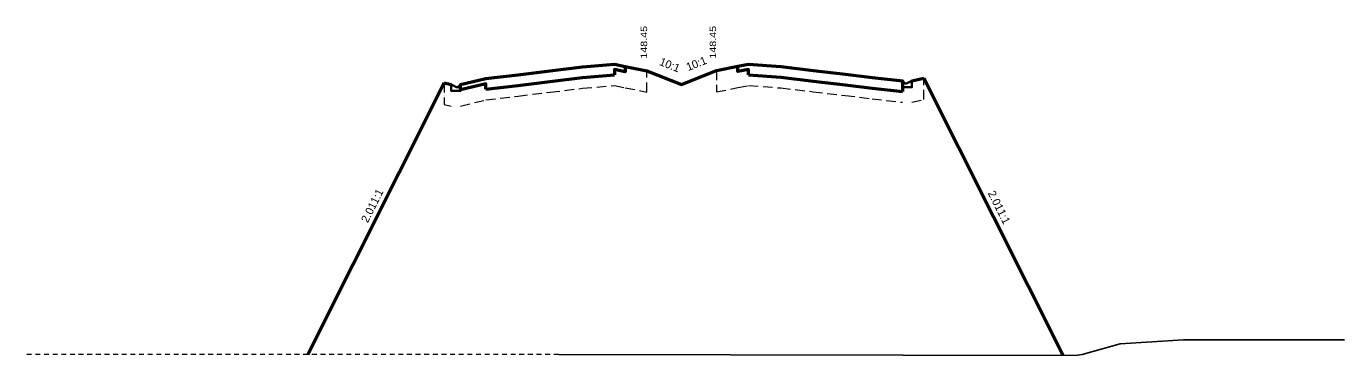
# Model space of a CAD drawing. Extents: x 72769 to 76375, y 67856 to 87579.
# Drawn here: x 75693.9 to 76188.2, y 76670.6 to 76794 of the extents above; entities that cross this region are included whole.
import ezdxf
from ezdxf.enums import TextEntityAlignment as Align

# ---------------------------------------------------------------- set-up
doc = ezdxf.new("R2010")
doc.units = 0
doc.header["$LTSCALE"] = 1.2
doc.linetypes.add('MEDIUM_DASHED', pattern=[4.5, 3, -1.5])
doc.linetypes.add('SHORT_DASHED', pattern=[2.7, 1.5, -1.2])
for name, color, linetype, lineweight in [('1', 7, 'Continuous', 53), ('10', 7, 'Continuous', 53), ('11', 7, 'Continuous', 53), ('12', 7, 'Continuous', 53), ('13', 7, 'MEDIUM_DASHED', 13), ('61', 7, 'Continuous', 25)]:
    doc.layers.add(name, color=color, linetype=linetype, lineweight=lineweight)
doc.layers.add('21', color=7, linetype='Continuous')
doc.layers.add('50', color=7, linetype='Continuous')

msp = doc.modelspace()

# ---------------------------------------------------------------- linework, layer by layer
at = {"layer": '1'}
for p, q in [((75890.316, 76777.315), (75902.382, 76778.775)), ((75902.382, 76778.775), (75914.449, 76779.754)), ((75964.725, 76779.833), (75976.79, 76778.892)), ((75976.79, 76778.892), (75988.855, 76777.47)), ((75866.184, 76774.395), (75878.251, 76775.855)), ((75878.251, 76775.855), (75890.316, 76777.315)), ((75890.316, 76773.315), (75902.382, 76774.775)), ((75902.382, 76774.775), (75914.449, 76775.754)), ((75964.725, 76775.833), (75976.79, 76774.892)), ((75976.79, 76774.892), (75988.855, 76773.47)), ((75988.855, 76777.47), (76000.922, 76776.048)), ((76000.922, 76776.048), (76010.981, 76774.862)), ((76010.981, 76774.862), (76022.42, 76773.514)), ((75866.184, 76770.395), (75878.251, 76771.855)), ((75878.251, 76771.855), (75890.316, 76773.315)), ((75988.855, 76773.47), (76000.922, 76772.048)), ((76000.922, 76772.048), (76010.981, 76770.862)), ((76010.981, 76770.862), (76022.42, 76769.514))]:
    msp.add_line(p, q, dxfattribs=at)
at = {"layer": '10'}
for p, q in [((75918.473, 76778.959), (75926.517, 76777.368)), ((75952.66, 76777.41), (75960.704, 76779.025)), ((76025.954, 76773.514), (76030.374, 76774.569)), ((75850.601, 76772.749), (75853.213, 76772.125))]:
    msp.add_line(p, q, dxfattribs=at)
at = {"layer": '10', "lineweight": 35}
for points in [[(75856.722, 76772.125), (75856.722, 76769.792), (75853.213, 76769.792), (75853.213, 76772.125), (75855.219, 76771.125), (75855.72, 76771.125)], [(76022.42, 76773.514), (76023.43, 76772.514), (76023.935, 76772.514), (76025.954, 76773.514), (76025.954, 76771.181), (76022.42, 76771.181)]]:
    msp.add_lwpolyline(points, close=True, dxfattribs=at)
at = {"layer": '11'}
for points in [[(75914.449, 76779.754), (75918.473, 76778.959), (75918.473, 76776.959), (75914.449, 76777.754), (75914.449, 76775.754)], [(75964.725, 76775.833), (75964.725, 76777.833), (75960.704, 76777.025), (75960.704, 76779.025), (75964.725, 76779.833)], [(75866.184, 76770.395), (75866.184, 76772.395), (75856.722, 76770.125), (75856.722, 76772.125), (75866.184, 76774.395)], [(76022.42, 76773.514), (76022.42, 76773.514), (76022.42, 76771.514), (76022.42, 76771.514), (76022.42, 76769.514)]]:
    msp.add_lwpolyline(points, dxfattribs=at)
at = {"layer": '12'}
for p, q in [((76030.374, 76774.569), (76082.661, 76670.577)), ((75799.42, 76670.949), (75850.601, 76772.749))]:
    msp.add_line(p, q, dxfattribs=at)
msp.add_lwpolyline([(75926.517, 76777.368), (75939.536, 76772.189), (75952.66, 76777.41)], dxfattribs=at)
at = {"layer": '13'}
for p, q in [((75878.251, 76767.855), (75890.316, 76769.315)), ((75890.316, 76769.315), (75902.382, 76770.775)), ((75902.382, 76770.775), (75914.449, 76771.754)), ((75914.449, 76771.754), (75918.473, 76770.959)), ((75960.704, 76771.025), (75964.725, 76771.833)), ((75964.725, 76771.833), (75976.79, 76770.892)), ((75976.79, 76770.892), (75988.855, 76769.47)), ((75988.855, 76769.47), (76000.922, 76768.048)), ((75856.722, 76764.125), (75866.184, 76766.395)), ((75866.184, 76766.395), (75878.251, 76767.855)), ((76000.922, 76768.048), (76010.981, 76766.862)), ((76010.981, 76766.862), (76022.42, 76765.514)), ((76022.42, 76765.514), (76022.42, 76765.514))]:
    msp.add_line(p, q, dxfattribs=at)
for points in [[(75918.473, 76770.959), (75926.517, 76769.368), (75926.517, 76777.368)], [(75952.66, 76777.41), (75952.66, 76769.41), (75960.704, 76771.025)], [(76025.954, 76765.514), (76030.374, 76766.569), (76030.374, 76774.569)], [(75850.601, 76772.749), (75850.601, 76764.749), (75853.213, 76764.125)]]:
    msp.add_lwpolyline(points, dxfattribs=at)
at = {"layer": '61', "linetype": 'SHORT_DASHED', "lineweight": 13}
msp.add_line((75893.484, 76670.949), (75693.88, 76670.949), dxfattribs=at)
at = {"layer": '61'}
msp.add_lwpolyline([(75893.484, 76670.949), (76087.104, 76670.569), (76089.779, 76670.949), (76104.021, 76674.949), (76127.779, 76676.549), (76188.205, 76676.549)], dxfattribs=at)

# ---------------------------------------------------------------- texts
at = {"layer": '21', "width": 1.25}
for p in [(75926.657, 76780.754), (75952.515, 76780.754)]:
    msp.add_text(' 148.45', height=2.4, rotation=90, dxfattribs=at).set_placement(p)
at = {"layer": '50'}
for s, rotation, p in [('10:1', 338.307, (75934.613, 76778.148)), ('10:1', 21.693, (75945.673, 76778.631)), ('2.011:1', 63.309, (75824.904, 76726.104)), ('2.011:1', 296.693, (76057.301, 76725.481))]:
    msp.add_text(s, height=3, rotation=rotation, dxfattribs=at).set_placement(p, align=Align.CENTER)

doc.saveas('drawing.dxf')
